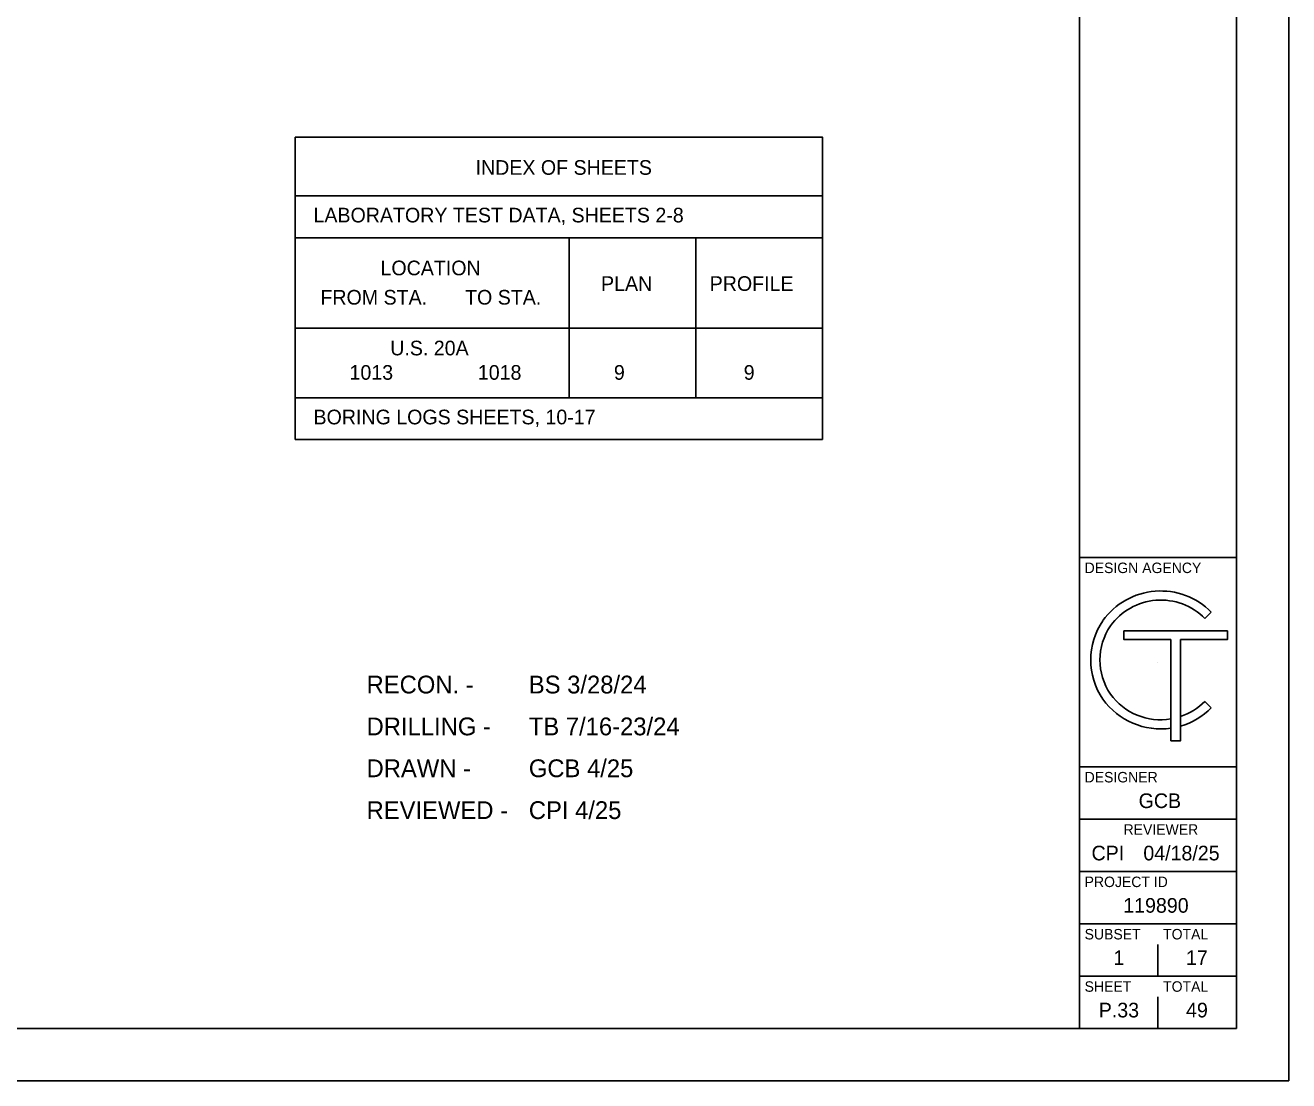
# Model space of a CAD drawing. Extents: x -21.7 to 34, y 0 to 22.
# Drawn here: x 21.93 to 34, y 0 to 10.08 of the extents above; entities that cross this region are included whole.
import ezdxf

# ---------------------------------------------------------------- set-up
doc = ezdxf.new("R2010")
doc.units = 0
for name, color, linetype in [('SH_Border', 7, 'Continuous'), ('SH_Cut_Line', 7, 'Continuous'), ('SH_Data', 7, 'Continuous'), ('SH_Text', 7, 'Continuous')]:
    doc.layers.add(name, color=color, linetype=linetype)

msp = doc.modelspace()

# ---------------------------------------------------------------- linework, layer by layer
at = {"layer": 'SH_Border'}
for p, q in [((32, 0.5), (32, 21.5)), ((32, 5), (33.5, 5)), ((32, 3), (33.5, 3)), ((32, 2.5), (33.5, 2.5)), ((32, 2), (33.5, 2)), ((32, 1.5), (33.5, 1.5)), ((32, 1), (33.5, 1))]:
    msp.add_line(p, q, dxfattribs=at)
msp.add_lwpolyline([(1.5, 21.5), (33.5, 21.5), (33.5, 0.5), (1.5, 0.5)], close=True, dxfattribs=at)
at = {"layer": 'SH_Cut_Line'}
msp.add_lwpolyline([(0, 0), (34, 0), (34, 22), (0, 22)], close=True, dxfattribs=at)
at = {"layer": 'SH_Data'}
for p, q in [((24.507, 9.016), (24.507, 6.125)), ((24.507, 8.454), (29.545, 8.454)), ((24.507, 8.054), (29.545, 8.054)), ((27.127, 8.054), (27.127, 6.525)), ((28.336, 6.525), (28.336, 8.054)), ((24.507, 7.19), (29.545, 7.19)), ((24.507, 6.525), (29.545, 6.525)), ((24.507, 6.125), (29.545, 6.125)), ((32.75, 4), (32.75, 4)), ((32.75, 1), (32.75, 1.3)), ((32.75, 0.5), (32.75, 0.8)), ((32.375, 0.675), (32.375, 0.675))]:
    msp.add_line(p, q, dxfattribs=at)
msp.add_lwpolyline([(29.545, 6.125), (29.545, 9.016), (24.507, 9.016)], dxfattribs=at)
at = {"layer": 'SH_Text'}
for p, q in [((33.26, 4.477), (33.198, 4.416)), ((33.26, 4.477), (33.198, 4.416)), ((33.414, 4.297), (32.425, 4.297)), ((32.425, 4.297), (32.425, 4.215)), ((33.414, 4.215), (33.414, 4.297)), ((32.425, 4.215), (32.875, 4.215)), ((32.875, 4.215), (32.875, 3.248)), ((32.967, 3.248), (32.967, 4.215)), ((32.967, 4.215), (33.414, 4.215)), ((33.198, 3.624), (33.26, 3.563)), ((33.198, 3.624), (33.26, 3.563)), ((32.875, 3.457), (32.875, 3.368)), ((32.875, 3.457), (32.875, 3.368)), ((32.967, 3.388), (32.967, 3.48)), ((32.967, 3.388), (32.967, 3.48)), ((32.875, 3.248), (32.967, 3.248))]:
    msp.add_line(p, q, dxfattribs=at)
msp.add_lwpolyline([(32.875, 4.215), (32.875, 3.248), (32.967, 3.248), (32.967, 4.215), (33.414, 4.215), (33.414, 4.297), (32.425, 4.297), (32.425, 4.215)], close=True, dxfattribs=at)
for centre, radius, start, end in [((32.777, 3.999), 0.68, 44.7027, 144.3276), ((32.777, 3.999), 0.68, 44.7027, 144.3276), ((32.777, 3.999), 0.593, 44.7362, 144.1102), ((32.777, 3.999), 0.593, 44.7362, 144.1102), ((32.775, 4.02), 0.666, 145.7329, 214.2671), ((32.775, 4.02), 0.666, 145.7329, 214.2671), ((32.775, 4.02), 0.579, 145.7266, 214.2734), ((32.775, 4.02), 0.579, 145.7266, 214.2734), ((32.777, 4.041), 0.68, 215.6724, 278.2613), ((32.777, 4.041), 0.68, 215.6724, 278.2613), ((32.777, 4.041), 0.593, 215.8898, 279.4882), ((32.777, 4.041), 0.593, 215.8898, 279.4882), ((32.777, 4.041), 0.593, 288.6992, 315.2638), ((32.777, 4.041), 0.593, 288.6992, 315.2638), ((32.777, 4.041), 0.68, 286.2291, 315.2973), ((32.777, 4.041), 0.68, 286.2291, 315.2973)]:
    msp.add_arc(centre, radius, start, end, dxfattribs=at)

# ---------------------------------------------------------------- texts
at = {"layer": 'SH_Data'}
for s, height, p in [('DESIGN AGENCY', 0.1, (32.05, 4.85)), ('DESIGNER', 0.1, (32.05, 2.85)), ('GCB', 0.14, (32.566, 2.605)), ('REVIEWER', 0.1, (32.422, 2.35)), ('CPI', 0.14, (32.116, 2.105)), ('04/18/25', 0.14, (32.611, 2.105)), ('PROJECT ID', 0.1, (32.05, 1.85)), ('SUBSET', 0.1, (32.05, 1.35)), ('TOTAL', 0.1, (32.8, 1.35)), ('1', 0.14, (32.325, 1.105)), ('17', 0.14, (33.018, 1.105)), ('SHEET', 0.1, (32.05, 0.85)), ('TOTAL', 0.1, (32.8, 0.85)), ('P.33', 0.14, (32.185, 0.605)), ('49', 0.14, (33.019, 0.605))]:
    msp.add_text(s, height=height, dxfattribs=at).set_placement(p)
at = {"layer": 'SH_Text'}
for s, height, p in [('INDEX OF SHEETS', 0.14, (26.231, 8.655)), ('LABORATORY TEST DATA, SHEETS 2-8', 0.14, (24.683, 8.2)), ('LOCATION', 0.14, (25.323, 7.695)), ('PLAN', 0.14, (27.43, 7.546)), ('PROFILE', 0.14, (28.468, 7.546)), ('FROM STA.', 0.14, (24.749, 7.415)), ('TO STA.', 0.14, (26.131, 7.415)), ('   U.S. 20A   ', 0.14, (25.26, 6.93)), ('     1013     ', 0.14, (24.767, 6.697)), ('     1018     ', 0.14, (25.993, 6.697)), (' 9 ', 0.14, (27.501, 6.697)), (' 9 ', 0.14, (28.741, 6.697)), ('BORING LOGS SHEETS, 10-17', 0.14, (24.683, 6.271)), ('RECON. -', 0.17, (25.19, 3.7)), ('BS 3/28/24                ', 0.17, (26.74, 3.7)), ('DRILLING -', 0.17, (25.19, 3.3)), ('TB 7/16-23/24             ', 0.17, (26.74, 3.3)), ('DRAWN -', 0.17, (25.19, 2.9)), ('GCB 4/25                  ', 0.17, (26.74, 2.9)), ('REVIEWED -', 0.17, (25.19, 2.5)), ('CPI 4/25                  ', 0.17, (26.74, 2.5)), ('119890', 0.14, (32.419, 1.605))]:
    msp.add_text(s, height=height, dxfattribs=at).set_placement(p)

doc.saveas('drawing.dxf')
